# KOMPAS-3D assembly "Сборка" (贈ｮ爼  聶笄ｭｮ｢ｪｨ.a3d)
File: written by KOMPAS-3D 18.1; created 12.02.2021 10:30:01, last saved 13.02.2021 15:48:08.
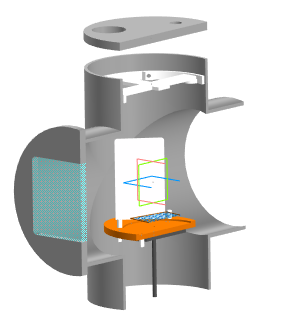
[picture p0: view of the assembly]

Document properties: Полное имя файла: C:\GoogleDrive\НИР\ИКИ\Компас\Сборка установки.a3d

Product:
- Part/product: Сборка
    Масса: 9.8357
  - Component [detail]: Деталь  | Масса: 0.160372; source file: Крестовина.m3d
  - Component [assembly]: Сборка  | Масса: 1.46022; source file: Фланец с окном.a3d
  - Component [detail]: Деталь  | Масса: 1.35822; source file: Верхний фланец.m3d
  - Component [detail]: Деталь  | Материал: Полипропилен  ГОСТ 26996-86 (density 900 kg/m3); Масса: 0.0192571; source file: Распорное кольцо.m3d
  - Component [detail]: Деталь  | Масса: 6.02592; source file: База вакуумной.m3d
  - Component [assembly]: Сборка  | Масса: 0.642195; source file: Сборка столика.a3d
  - Component [detail]: Деталь  | Масса: 0.169523; source file: Столик в вакуумной камере.m3d

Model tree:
1. Эскиз:2  (with: Элемент выдавливания:1, Элемент выдавливания:3, Элемент выдавливания:2, Элемент выдавливания:8, Элемент выдавливания:4, Элемент выдавливания:7)
     Расстояние = 20; Ориентация = 2

Referenced files in C:\GoogleDrive\НИР\ИКИ\Компас\: База вакуумной.m3d, Распорное кольцо.m3d, Верхний фланец.m3d, Фланец с окном.a3d, Сборка столика.a3d, Столик в вакуумной камере.m3d, Крестовина.m3d
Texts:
  Точка начала. Х
  Точка начала. Y
  Точка начала. Z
